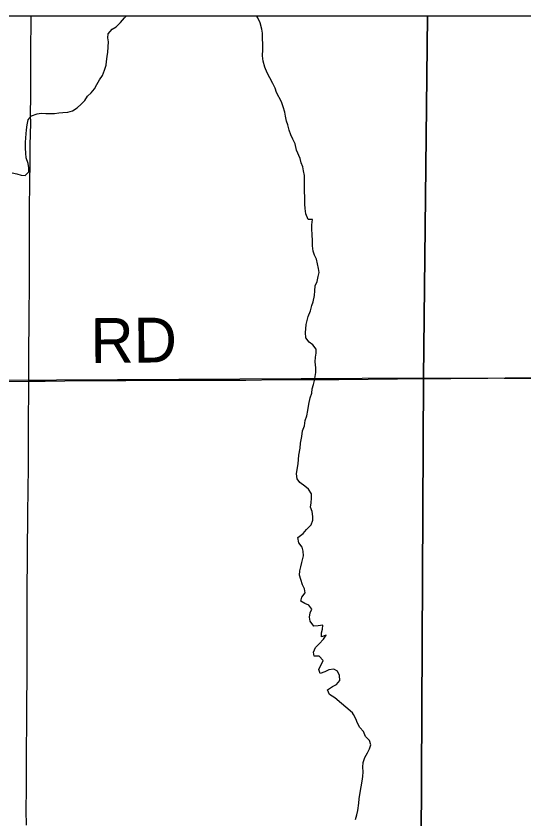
# Model space of a CAD drawing. Extents: x 0 to 34, y 0 to 22.
# Drawn here: x 5.97 to 6.615, y 19.882 to 20.9 of the extents above; entities that cross this region are included whole.
import ezdxf

# ---------------------------------------------------------------- set-up
doc = ezdxf.new("R2010")
doc.units = 0
for name, color, linetype in [('Default', 7, 'Continuous'), ('GM_X_Minor_River', 7, 'Continuous'), ('GM_X_Section', 7, 'Continuous'), ('GM_X_Township_Road', 7, 'Continuous'), ('GM_X_Township_Road_Text', 7, 'Continuous'), ('SH_Cut_Line', 7, 'Continuous')]:
    doc.layers.add(name, color=color, linetype=linetype)

msp = doc.modelspace()

# ---------------------------------------------------------------- linework, layer by layer
at = {"layer": 'Default'}
msp.add_lwpolyline([(8.9, 20.9), (2.6032, 20.9), (2.6032, 20.8721), (2.6224, 19.9515), (2.6281, 18.8843)], dxfattribs=at)
for points in [[(6.4922, 20.9), (5.4779, 20.9), (5.4771, 20.4356), (6.4874, 20.4413)], [(7.5179, 20.9), (6.4922, 20.9), (6.4874, 20.4413), (7.5127, 20.4367)]]:
    msp.add_lwpolyline(points, close=True, dxfattribs=at)
at = {"layer": 'GM_X_Minor_River'}
for points in [[(5.9651, 20.7013), (5.9712, 20.6998), (5.9765, 20.6983), (5.9814, 20.6979), (5.9863, 20.7025), (5.9863, 20.7075), (5.9852, 20.7128), (5.9828, 20.72), (5.9824, 20.7261), (5.982, 20.7325), (5.982, 20.7394), (5.9823, 20.7455), (5.9827, 20.7504), (5.9834, 20.7557), (5.9841, 20.7622), (5.9852, 20.7683), (5.9898, 20.7733), (5.9966, 20.7759), (6.0019, 20.7767), (6.008, 20.7764), (6.019, 20.7764), (6.0243, 20.7772), (6.0292, 20.7776), (6.0357, 20.778), (6.0417, 20.7796), (6.0478, 20.7834), (6.0527, 20.788), (6.0572, 20.7929), (6.0606, 20.7983), (6.0655, 20.8025), (6.0697, 20.8078), (6.0727, 20.8132), (6.0761, 20.8189), (6.0798, 20.8246), (6.0825, 20.8315), (6.0843, 20.8376), (6.085, 20.8425), (6.0858, 20.8486), (6.0865, 20.8543), (6.0872, 20.8672), (6.0864, 20.8725), (6.0868, 20.8775), (6.092, 20.8832), (6.0973, 20.8863), (6.1026, 20.8916), (6.1075, 20.8977), (6.1097, 20.9)], [(6.3455, 20.5327), (6.3474, 20.5376), (6.3489, 20.5456), (6.3492, 20.5513), (6.3499, 20.5578), (6.3522, 20.5631), (6.3537, 20.5696), (6.3548, 20.5749), (6.354, 20.5798), (6.3525, 20.5855), (6.3513, 20.5916), (6.349, 20.5965), (6.3471, 20.6019), (6.3463, 20.6087), (6.3462, 20.6148), (6.3458, 20.6231), (6.3454, 20.6296), (6.3457, 20.6353), (6.3465, 20.6418), (6.3408, 20.6421), (6.3377, 20.6493), (6.3369, 20.6558), (6.3365, 20.6615), (6.3365, 20.671), (6.336, 20.6767), (6.3364, 20.6828), (6.3363, 20.6976), (6.3351, 20.7037), (6.334, 20.7086), (6.332, 20.714), (6.3309, 20.7193), (6.3259, 20.7299), (6.3243, 20.7379), (6.3213, 20.7439), (6.319, 20.7493), (6.3166, 20.7553), (6.3151, 20.7618), (6.3132, 20.7667), (6.312, 20.7728), (6.3112, 20.7781), (6.3093, 20.785), (6.307, 20.791), (6.3008, 20.8032), (6.2989, 20.8085), (6.2962, 20.8145), (6.2924, 20.8214), (6.2889, 20.8278), (6.2859, 20.835), (6.2836, 20.8426), (6.2828, 20.8495), (6.2831, 20.8575), (6.283, 20.8784), (6.2822, 20.8833), (6.2799, 20.8913), (6.2768, 20.8977), (6.2758, 20.9)], [(6.3973, 20.0161), (6.3747, 20.0351), (6.3679, 20.0396), (6.3652, 20.0453), (6.3716, 20.0495), (6.3769, 20.0522), (6.381, 20.0572), (6.3806, 20.0636), (6.3783, 20.0689), (6.3734, 20.0716), (6.3669, 20.0708), (6.362, 20.0681), (6.3563, 20.0662), (6.3544, 20.0711), (6.3597, 20.0825), (6.3547, 20.0882), (6.3486, 20.0882), (6.3478, 20.0931), (6.3501, 20.0992), (6.355, 20.1038), (6.3603, 20.1095), (6.3637, 20.1149), (6.3576, 20.1126), (6.3576, 20.1175), (6.3591, 20.1225), (6.3594, 20.1274), (6.3537, 20.1266), (6.348, 20.1262), (6.3435, 20.1323), (6.3427, 20.1376), (6.3434, 20.1429), (6.3457, 20.1479), (6.3415, 20.1528), (6.3365, 20.1551), (6.3316, 20.1577), (6.3327, 20.163), (6.3372, 20.1684), (6.3364, 20.1737), (6.3337, 20.1786), (6.3314, 20.1855), (6.3299, 20.1908), (6.3302, 20.1965), (6.3317, 20.2014), (6.3328, 20.2068), (6.3351, 20.2155), (6.3346, 20.2212), (6.3331, 20.2265), (6.3289, 20.2318), (6.3277, 20.2387), (6.3345, 20.2436), (6.3387, 20.2486), (6.3447, 20.2547), (6.3466, 20.2604), (6.3469, 20.2654), (6.3458, 20.2714), (6.3438, 20.2771), (6.3446, 20.2825), (6.3449, 20.2886), (6.3449, 20.2939), (6.3414, 20.2999), (6.3365, 20.3037), (6.3304, 20.3083), (6.3269, 20.3132), (6.3262, 20.3193), (6.3269, 20.325), (6.328, 20.3322), (6.3291, 20.3429), (6.3305, 20.352), (6.3313, 20.3581), (6.3327, 20.3668), (6.3338, 20.3737), (6.3361, 20.3801), (6.3372, 20.387), (6.339, 20.3931), (6.3405, 20.3996), (6.3416, 20.4075), (6.3435, 20.4159), (6.3454, 20.4216), (6.3461, 20.427), (6.3476, 20.4327), (6.3491, 20.4376), (6.3498, 20.4426), (6.3505, 20.4479), (6.3505, 20.4536), (6.3497, 20.4616), (6.35, 20.4673), (6.3512, 20.4722), (6.3511, 20.4775), (6.3469, 20.4829), (6.342, 20.4863), (6.3378, 20.4919), (6.3374, 20.4984), (6.3377, 20.5033), (6.3384, 20.5087), (6.3396, 20.514), (6.3407, 20.5189), (6.3437, 20.5262), (6.3455, 20.5327)], [(6.4009, 19.8811), (6.4028, 19.8868), (6.404, 19.8925), (6.4051, 19.9016), (6.4058, 19.9073), (6.407, 19.9153), (6.4081, 19.9222), (6.4096, 19.9294), (6.4104, 19.9355), (6.4107, 19.9416), (6.4103, 19.9473), (6.4107, 19.9533), (6.4126, 19.9594), (6.416, 19.9655), (6.4187, 19.9705), (6.4206, 19.9758), (6.4186, 19.9811), (6.4137, 19.986), (6.411, 19.9925), (6.4064, 19.9978), (6.4037, 20.0032), (6.4014, 20.0085), (6.3983, 20.0142), (6.3973, 20.0161)]]:
    msp.add_lwpolyline(points, dxfattribs=at)
at = {"layer": 'GM_X_Section'}
for points in [[(5.4771, 20.4356), (6.4874, 20.4413), (6.4824, 19.4291), (5.472, 19.4291)], [(6.4874, 20.4413), (7.5127, 20.4367), (7.5091, 19.4296), (6.4824, 19.4291)]]:
    msp.add_lwpolyline(points, close=True, dxfattribs=at)
at = {"layer": 'GM_X_Township_Road'}
for points in [[(5.9863, 20.4368), (5.9863, 20.4546), (5.9862, 20.467), (5.9864, 20.4825), (5.9866, 20.5043), (5.9867, 20.526), (5.987, 20.5539), (5.9872, 20.5726), (5.987, 20.6067), (5.987, 20.6192), (5.987, 20.6533), (5.9877, 20.6905), (5.988, 20.7122), (5.9881, 20.7371), (5.9882, 20.7495), (5.9886, 20.765), (5.9883, 20.7744), (5.9882, 20.7836), (5.9886, 20.7898), (5.9887, 20.796), (5.9888, 20.8115), (5.9888, 20.8332), (5.9889, 20.8518), (5.9892, 20.9)], [(5.9863, 20.4368), (6.007, 20.437), (6.0318, 20.4373), (6.0846, 20.4377), (6.1094, 20.4378), (6.1343, 20.438), (6.1809, 20.4381), (6.2182, 20.4382), (6.2399, 20.4383), (6.2617, 20.4383), (6.302, 20.4388), (6.3206, 20.439), (6.3517, 20.4391), (6.3796, 20.4392), (6.4169, 20.4395), (6.4542, 20.44), (6.4914, 20.4403), (6.522, 20.4403), (6.5506, 20.4405), (6.569, 20.4408), (6.5908, 20.4409), (6.6746, 20.4412)], [(5.3193, 20.431), (5.324, 20.4312), (5.3271, 20.4314), (5.3363, 20.4318), (5.3673, 20.4324), (5.3983, 20.4327), (5.4139, 20.433), (5.4294, 20.4331), (5.4946, 20.4328), (5.5288, 20.4329), (5.563, 20.4332), (5.6034, 20.4334), (5.6407, 20.4339), (5.6748, 20.4342), (5.709, 20.4343), (5.74, 20.4346), (5.7648, 20.435), (5.7896, 20.4354), (5.8424, 20.4359), (5.8859, 20.436), (5.9604, 20.4366), (5.9853, 20.4367), (5.9863, 20.4368)], [(5.9831, 19.8738), (5.983, 19.8925), (5.9833, 19.9204), (5.9831, 19.9329), (5.9833, 19.9484), (5.9832, 19.9577), (5.9836, 20.0136), (5.9839, 20.0757), (5.984, 20.1161), (5.9843, 20.1658), (5.9844, 20.2186), (5.9851, 20.2683), (5.9853, 20.2993), (5.9858, 20.3273), (5.9859, 20.3677), (5.986, 20.3925), (5.9863, 20.4204), (5.9863, 20.4368)]]:
    msp.add_lwpolyline(points, dxfattribs=at)
at = {"layer": 'SH_Cut_Line'}
msp.add_lwpolyline([(8.9, 20.9), (2.6032, 20.9), (2.6032, 20.8721), (2.6224, 19.9515), (2.6281, 18.8843), (2.6292, 18.3794), (2.6263, 18.3795), (2.6204, 18.3797), (2.6161, 18.3799), (2.6118, 18.3803), (2.6122, 18.05), (2.6129, 17.8818), (2.6231, 17.3771), (2.6332, 16.3685)], dxfattribs=at)

# ---------------------------------------------------------------- texts
at = {"layer": 'GM_X_Township_Road_Text'}
msp.add_text('RD', height=0.05682, rotation=0.4939, dxfattribs=at).set_placement((6.0647, 20.4599))

doc.saveas('drawing.dxf')
